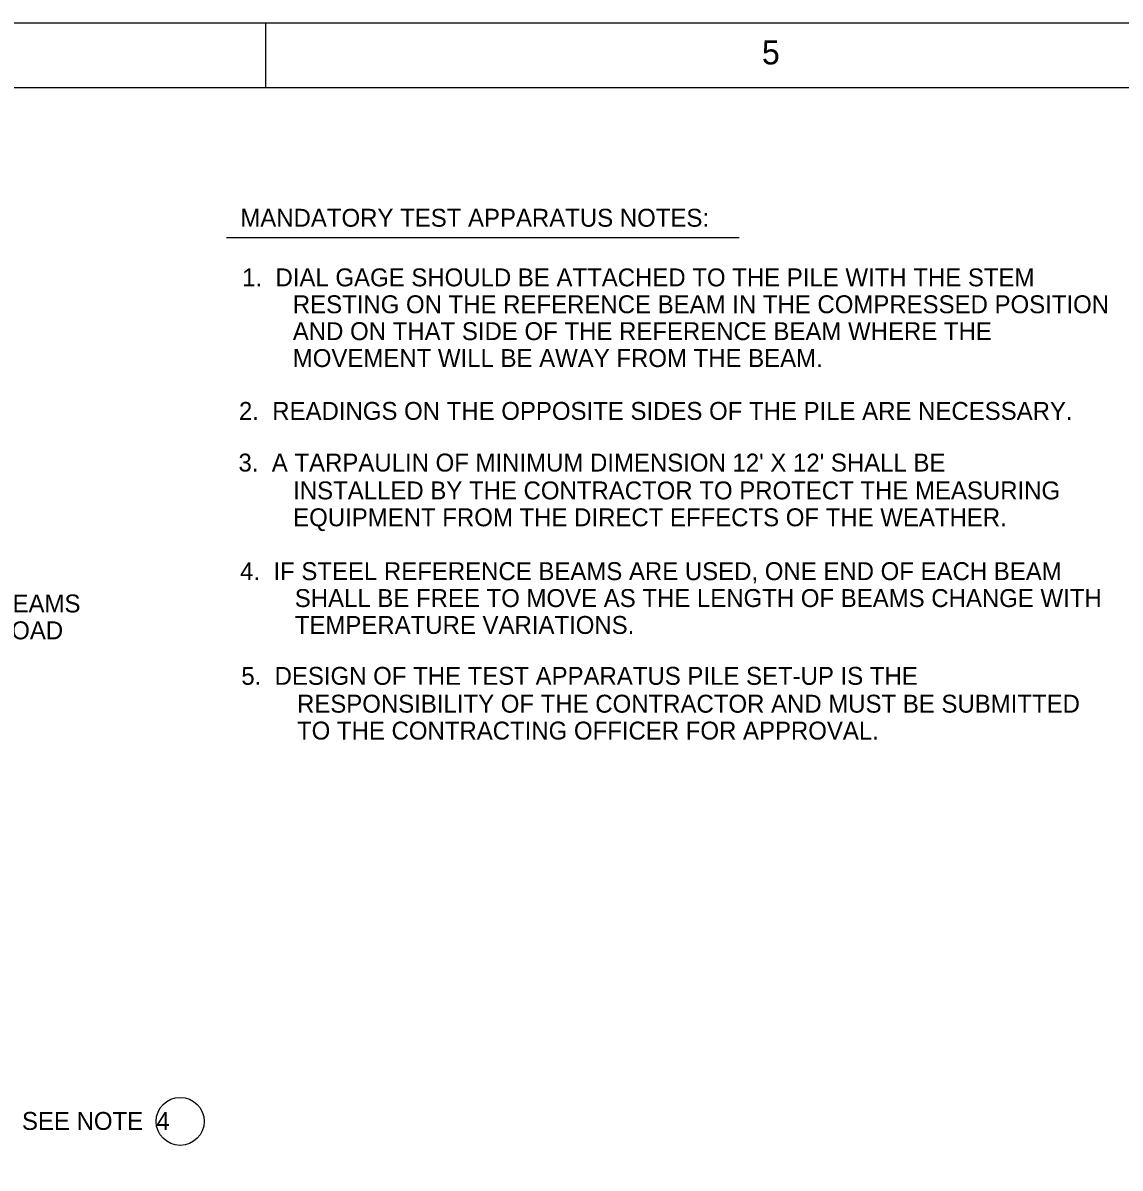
# Model space of a CAD drawing. Extents: x 22378.6 to 22422.6, y 22377.7 to 22411.7.
# Drawn here: x 22409.64 to 22418.21, y 22402.72 to 22411.66 of the extents above; entities that cross this region are included whole.
import ezdxf

# ---------------------------------------------------------------- set-up
doc = ezdxf.new("R2010")
doc.units = 0
for name, color, linetype in [('Level 1', 7, 'Continuous'), ('Level 10', 7, 'Continuous'), ('Level 4', 7, 'Continuous'), ('Level 7', 7, 'Continuous'), ('Level 9', 7, 'Continuous')]:
    doc.layers.add(name, color=color, linetype=linetype)

msp = doc.modelspace()

# ---------------------------------------------------------------- linework, layer by layer
at = {"layer": 'Level 1'}
msp.add_lwpolyline([(22378.6294, 22411.6592), (22422.6454, 22411.6592), (22422.6454, 22377.6512), (22378.6294, 22377.6512)], close=True, dxfattribs=at)
at = {"layer": 'Level 10'}
msp.add_line((22411.5334, 22411.1552), (22411.5334, 22411.6592), dxfattribs=at)
at = {"layer": 'Level 7'}
msp.add_line((22411.2256, 22409.9845), (22415.2325, 22409.9845), dxfattribs=at)
msp.add_circle((22410.8645, 22403.0809), 0.1875, dxfattribs=at)
at = {"layer": 'Level 9'}
msp.add_line((22380.1294, 22411.1552), (22419.3934, 22411.1552), dxfattribs=at)

# ---------------------------------------------------------------- texts
at = {"layer": 'Level 1'}
msp.add_text('5', height=0.1873, dxfattribs=at).set_placement((22415.4094, 22411.3352))
at = {"layer": 'Level 4'}
for s, p in [('MANDATORY TEST APPARATUS NOTES:', (22411.3345, 22410.0674)), ('1.  DIAL GAGE SHOULD BE ATTACHED TO THE PILE WITH THE STEM', (22411.349, 22409.6018)), ('RESTING ON THE REFERENCE BEAM IN THE COMPRESSED POSITION', (22411.7445, 22409.3918)), ('AND ON THAT SIDE OF THE REFERENCE BEAM WHERE THE', (22411.7445, 22409.1818)), ('MOVEMENT WILL BE AWAY FROM THE BEAM.', (22411.7445, 22408.9718)), ('2.  READINGS ON THE OPPOSITE SIDES OF THE PILE ARE NECESSARY.', (22411.3238, 22408.559)), ("3.  A TARPAULIN OF MINIMUM DIMENSION 12' X 12' SHALL BE", (22411.3201, 22408.1556)), ('INSTALLED BY THE CONTRACTOR TO PROTECT THE MEASURING', (22411.7473, 22407.9382)), ('EQUIPMENT FROM THE DIRECT EFFECTS OF THE WEATHER.', (22411.7473, 22407.7282)), ('4.  IF STEEL REFERENCE BEAMS ARE USED, ONE END OF EACH BEAM', (22411.3327, 22407.3075)), ('REACTOR BEAMS ', (22408.463, 22407.0552)), ('SHALL BE FREE TO MOVE AS THE LENGTH OF BEAMS CHANGE WITH', (22411.7599, 22407.0975)), ('TEMPERATURE VARIATIONS.', (22411.7599, 22406.8875)), ('FOR TEST LOAD', (22408.463, 22406.8454)), ('5.  DESIGN OF THE TEST APPARATUS PILE SET-UP IS THE ', (22411.3422, 22406.49)), ('RESPONSIBILITY OF THE CONTRACTOR AND MUST BE SUBMITTED', (22411.7773, 22406.2726)), ('TO THE CONTRACTING OFFICER FOR APPROVAL.', (22411.7773, 22406.0626)), ('SEE NOTE  4', (22409.6287, 22403.0142))]:
    msp.add_text(s, height=0.14, dxfattribs=at).set_placement(p)

doc.saveas('drawing.dxf')
